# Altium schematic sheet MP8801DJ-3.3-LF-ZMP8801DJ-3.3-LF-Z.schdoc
size 127 x 101 mm
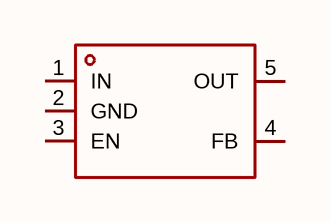
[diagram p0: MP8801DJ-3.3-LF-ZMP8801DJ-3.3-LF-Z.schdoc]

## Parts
U?  mp8801dj-3.3-lf-z  [TSOT-23-5_L2.9-W1.6-P0.95-LS2.8-BR]  (value not drawn)

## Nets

Not connected (* = marked no-connect by the designer): U? 1(IN) 2(GND) 3(EN) 4(FB) 5(OUT)

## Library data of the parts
U? = mp8801dj-3.3-lf-z: 输出极性:正极;工作电压:6.5V;输出电压:3.3V；1.25V~5V;输出电流:150mA;电源纹波抑制比(PSRR):70dB；30dB@(1MHz);输出类型:固定；可调;; Manufacturer: MPS(芯源); AddInBom: yes; ModelId: b5108020abe84f7bb0f3c398b43b6e0b; ModelName: TSOT-23-5_L2.9-W1.6-H1.00-LS2.8-P0.95; ModelTransform: 110.45568,114.173,0,180,0,0,0,0,0; Output Configuration: 正极; Voltage - Supply: 6.5V; Output Current: 150mA; Voltage Dropout: 150mV@(150mA); standby current: 125uA; Output Type: 固定；可调; Number of Outputs: 1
